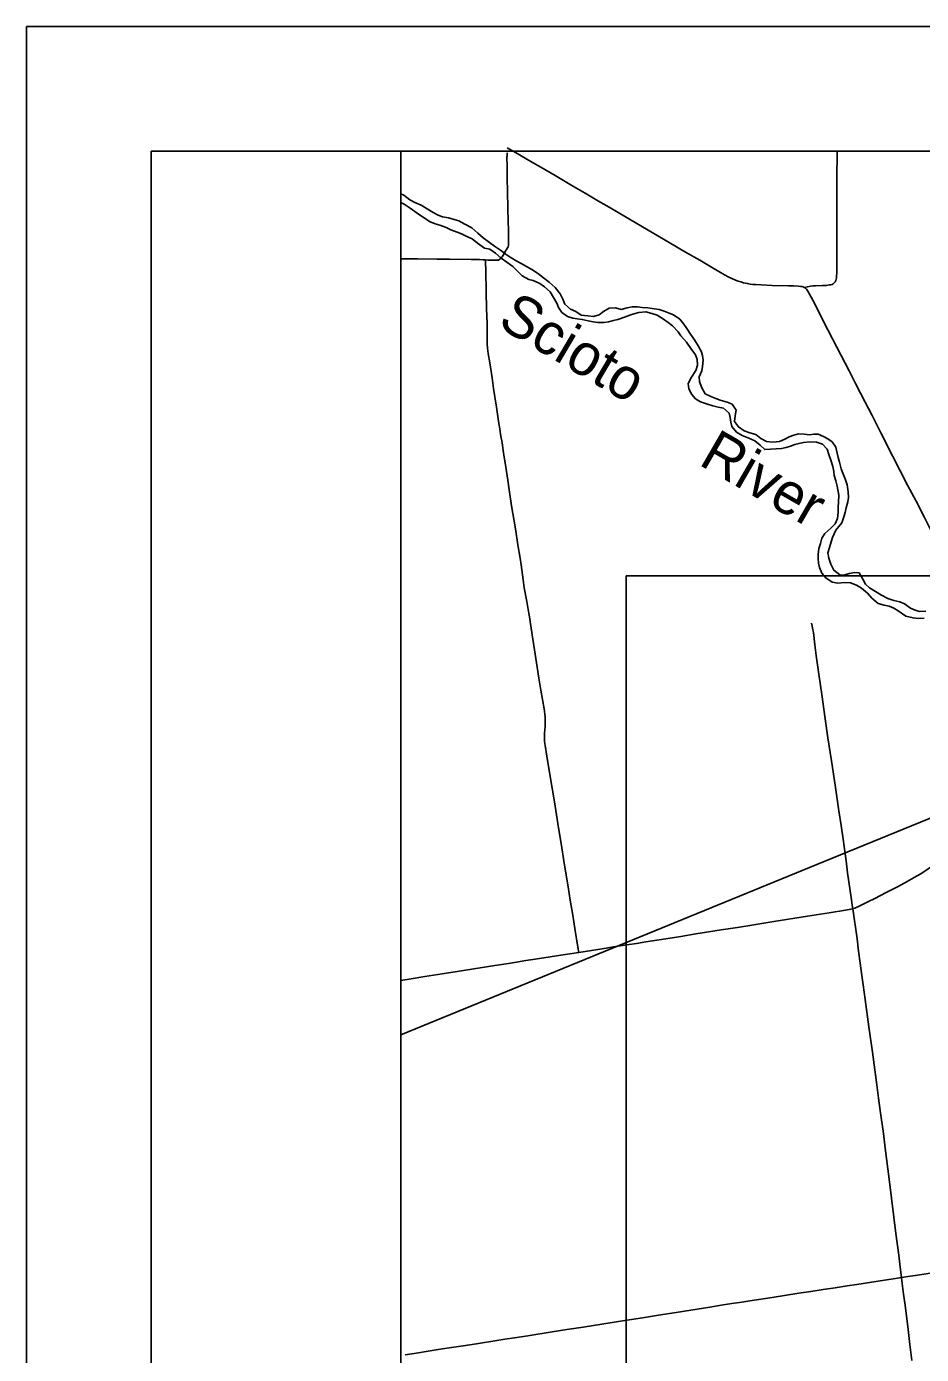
# Model space of a CAD drawing. Extents: x 0 to 680, y 0 to 440.
# Drawn here: x 0 to 71.7, y 333.5 to 440 of the extents above; entities that cross this region are included whole.
import ezdxf

# ---------------------------------------------------------------- set-up
doc = ezdxf.new("R2010")
doc.units = 0
for name, color, linetype in [('GM_X_County_Road', 7, 'Continuous'), ('GM_X_Major_River', 7, 'Continuous'), ('GM_X_Major_River_Text', 7, 'Continuous'), ('GM_X_Township_Road', 7, 'Continuous'), ('MT_P_Text', 7, 'Continuous'), ('RD_X_RR_2', 7, 'Continuous'), ('SH_Border', 7, 'Continuous'), ('SH_Cut_Line', 7, 'Continuous'), ('SH_Text', 7, 'Continuous')]:
    doc.layers.add(name, color=color, linetype=linetype)

msp = doc.modelspace()

# ---------------------------------------------------------------- linework, layer by layer
at = {"layer": 'GM_X_County_Road'}
for points in [[(38.61, 424.19), (38.61, 424.3), (38.61, 424.41), (38.6, 424.51), (38.6, 424.62), (38.6, 424.73), (38.6, 424.84), (38.59, 424.95), (38.59, 425.06), (38.59, 425.17), (38.58, 425.27), (38.58, 425.38), (38.58, 425.49), (38.57, 425.6), (38.57, 425.71), (38.57, 425.82), (38.57, 425.93), (38.57, 426.04), (38.56, 426.15), (38.56, 426.26), (38.55, 426.37), (38.55, 426.48), (38.55, 426.59), (38.55, 426.7), (38.54, 426.8), (38.54, 426.91), (38.54, 427.02), (38.54, 427.13), (38.54, 427.24), (38.53, 427.35), (38.53, 427.46), (38.53, 427.57), (38.53, 427.68), (38.53, 427.79), (38.53, 427.9), (38.53, 428.01), (38.52, 428.12), (38.52, 428.23), (38.52, 428.34), (38.52, 428.45), (38.52, 428.56), (38.52, 428.67), (38.52, 428.78), (38.52, 428.88), (38.52, 428.99), (38.52, 429.1), (38.51, 429.21), (38.51, 429.32), (38.51, 429.43), (38.51, 429.54), (38.52, 429.61), (38.52, 429.71), (38.52, 429.82), (38.52, 429.86)], [(38.52, 430.26), (38.67, 430.19), (39.05, 429.99), (40.56, 429.1), (41.22, 428.71), (42.36, 428.05), (43.85, 427.17), (44.78, 426.63), (45.85, 426), (46.7, 425.5), (48.02, 424.74), (48.78, 424.29), (49.82, 423.68), (51.51, 422.68), (52.83, 421.91), (53.97, 421.25), (54.91, 420.7), (55.48, 420.36), (55.95, 420.08), (56.24, 419.93), (56.54, 419.79), (56.84, 419.66), (57.05, 419.58), (57.26, 419.51), (57.47, 419.45), (57.79, 419.38), (58.01, 419.34), (58.23, 419.32), (58.45, 419.3), (58.89, 419.27), (59.76, 419.24), (61.07, 419.2), (61.51, 419.19), (61.84, 419.18), (62.05, 419.16), (62.16, 419.14), (62.26, 419.11), (62.32, 419.08)], [(38.31, 421.84), (38.36, 421.93), (38.4, 422), (38.47, 422.12), (38.56, 422.24), (38.61, 422.34), (38.63, 422.43), (38.64, 422.55), (38.64, 422.66), (38.64, 422.77), (38.63, 422.88), (38.63, 422.99), (38.64, 423.09), (38.63, 423.2), (38.63, 423.31), (38.63, 423.42), (38.63, 423.53), (38.62, 423.64), (38.62, 423.75), (38.62, 423.86), (38.62, 423.97), (38.61, 424.08), (38.61, 424.19)], [(36.79, 421.29), (36.98, 421.27), (37.18, 421.26), (37.33, 421.25), (37.66, 421.25), (37.83, 421.27), (37.95, 421.35), (38.03, 421.45), (38.12, 421.54), (38.21, 421.67), (38.28, 421.8), (38.31, 421.84)], [(30, 421.38), (30.49, 421.38), (31.37, 421.37), (32.9, 421.35), (33.89, 421.34), (35.64, 421.32), (36.3, 421.31), (36.59, 421.3), (36.79, 421.29)], [(62.32, 419.08), (62.36, 419.07), (62.44, 419.01), (62.52, 418.94), (62.58, 418.86), (62.64, 418.77), (62.9, 418.29), (63.16, 417.81), (63.89, 416.34), (65.3, 413.61), (65.94, 412.37), (66.45, 411.37), (66.85, 410.59), (67.21, 409.88), (67.75, 408.85), (68.48, 407.4), (69.45, 405.51), (70.63, 403.21), (71.3, 401.92), (71.95, 400.66), (72.5, 399.6), (73.05, 398.53), (73.79, 397.06), (74.31, 396.05)], [(44.26, 365.73), (44.78, 365.81), (46.29, 366.05), (47.05, 366.18), (47.59, 366.25), (48.13, 366.33), (48.89, 366.45), (49.64, 366.57), (50.72, 366.74), (51.59, 366.88), (52.45, 367.02), (53.64, 367.21), (54.5, 367.35), (55.69, 367.54), (56.99, 367.74), (58.29, 367.94), (59.91, 368.2), (62.61, 368.63), (64.34, 368.9), (65.64, 369.11), (66.07, 369.19), (66.23, 369.23)], [(30, 363.48), (30.84, 363.61), (31.92, 363.79), (33.32, 364.02), (34.51, 364.21), (36.35, 364.49), (37.54, 364.68), (38.62, 364.85), (39.27, 364.95), (40.02, 365.07), (40.78, 365.19), (41.97, 365.37), (42.83, 365.51), (44.26, 365.73)], [(70.97, 332.99), (70.81, 334.29), (70.66, 335.49), (70.42, 337.44), (70.3, 338.31), (70.16, 339.39), (70.13, 339.65)]]:
    msp.add_lwpolyline(points, dxfattribs=at)
at = {"layer": 'GM_X_Major_River'}
for points in [[(53.93, 411.54), (53.92, 411.89), (54.12, 412.38), (54.19, 412.72), (54.24, 413.25), (54.19, 413.6), (54.07, 413.95), (53.83, 414.38), (53.54, 414.87), (53.23, 415.32), (52.94, 415.78), (52.69, 416.12), (52.36, 416.54), (51.87, 416.87), (51.5, 417), (51.11, 417.17), (50.71, 417.29), (50.14, 417.39), (49.79, 417.43), (49.36, 417.47), (48.97, 417.52), (48.54, 417.51), (48.14, 417.43), (47.66, 417.31), (47.2, 417.44), (46.69, 417.4), (46.25, 417.14), (45.9, 416.87), (45.45, 416.73), (44.98, 416.79), (44.47, 416.86), (44.02, 417.13), (43.59, 417.33), (43.16, 417.72), (42.98, 418.14), (42.78, 418.57), (42.37, 419.07), (41.9, 419.5), (41.45, 419.84), (40.97, 420.23), (40.51, 420.52), (40.08, 420.76), (39.66, 421), (39.29, 421.19), (38.76, 421.5), (38.37, 421.77), (37.98, 422.07), (37.51, 422.38), (37.12, 422.68), (36.6, 423.06), (36.18, 423.42), (35.7, 423.85), (35.13, 424.16), (34.64, 424.41), (34.28, 424.53), (33.82, 424.65), (33.35, 424.74), (33, 424.86), (32.58, 425.09), (32.12, 425.39), (31.63, 425.66), (31.13, 425.88), (30.71, 426.11), (30.25, 426.47), (30, 426.58)], [(30, 425.89), (30.27, 425.75), (30.74, 425.43), (31.13, 425.16), (31.5, 424.89), (31.95, 424.59), (32.31, 424.36), (32.75, 424.17), (33.14, 424.06), (33.64, 423.87), (34.01, 423.7), (34.51, 423.5), (34.86, 423.36), (35.29, 423.17), (35.71, 422.96), (36.14, 422.62), (36.71, 422.23), (37.14, 422.14), (37.6, 421.83), (38.04, 421.41), (38.49, 421.1), (38.98, 420.74), (39.4, 420.32), (39.74, 420), (40.26, 419.72), (40.62, 419.63), (41.14, 419.4), (41.52, 419.13), (41.96, 418.71), (42.51, 417.82), (42.64, 417.47), (42.92, 417.07), (43.37, 416.73), (43.78, 416.6), (44.13, 416.55), (44.55, 416.51), (45.02, 416.4), (45.43, 416.32), (45.78, 416.27), (46.31, 416.26), (46.65, 416.31), (47.04, 416.42), (47.4, 416.49), (47.94, 416.7), (48.35, 416.84), (48.69, 416.96), (49.09, 417.06), (49.63, 417.11), (50.12, 416.99), (50.55, 416.85), (50.99, 416.58), (51.44, 416.27), (51.78, 416), (52.22, 415.51), (52.44, 415.18), (52.89, 414.68), (53.26, 414.17), (53.61, 413.66), (53.76, 413.28), (53.77, 412.83), (53.64, 412.42), (53.31, 411.87), (53.04, 411.38), (53.08, 410.95)], [(72.08, 393.1), (71.57, 393.09), (71.22, 393.18), (70.86, 393.35), (70.38, 393.69), (70.01, 393.85), (69.53, 393.95), (69.04, 394.12), (68.53, 394.4), (68.04, 394.69), (67.58, 394.98), (67.24, 395.28), (67.04, 395.67), (66.74, 396.17), (66.39, 396.21), (65.94, 396.13), (65.52, 395.99), (65.18, 396.03), (64.7, 396.38), (64.47, 396.87), (64.3, 397.35), (64.22, 397.79), (64.37, 398.2), (64.51, 398.66), (64.6, 399.02), (64.87, 399.59), (65.35, 400.2), (65.52, 400.67), (65.63, 401.03), (65.71, 401.4), (65.84, 401.87), (65.88, 402.23), (65.87, 402.67), (65.78, 403.23), (65.65, 403.63), (65.42, 404.17), (65.3, 404.53), (65.17, 405.05), (65.06, 405.44), (64.98, 405.78), (64.86, 406.26), (64.57, 406.69), (64.22, 406.94), (63.87, 407.11), (63.45, 407.29), (63.1, 407.29), (62.75, 407.26), (62.34, 407.29), (61.89, 407.34), (61.5, 407.23), (61.14, 407.09), (60.78, 406.89), (60.36, 406.71), (59.82, 406.65), (59.32, 406.72), (58.86, 406.95), (58.45, 407.28), (57.97, 407.41), (57.52, 407.57), (57.06, 407.88), (56.74, 408.31), (56.8, 408.78), (56.87, 409.24), (56.55, 409.72), (56.17, 409.86), (55.61, 410.02), (55.26, 410.17), (54.86, 410.32), (54.4, 410.55), (54.09, 411.08), (53.93, 411.54)], [(53.08, 410.95), (53.33, 410.49), (53.62, 410.14), (54.02, 409.9), (54.5, 409.74), (55.01, 409.58), (55.43, 409.47), (55.88, 409.38), (56.31, 409), (56.4, 408.65), (56.45, 408.26), (56.54, 407.91), (56.91, 407.47), (57.36, 407.19), (57.89, 406.97), (58.39, 406.78), (58.8, 406.43), (59.17, 406.06), (59.64, 406.09), (60.09, 406.12), (60.52, 406.15), (60.89, 406.22), (61.23, 406.35), (61.59, 406.47), (61.92, 406.56), (62.27, 406.63), (62.79, 406.69), (63.32, 406.67), (63.79, 406.49), (64.17, 406.09), (64.3, 405.67), (64.47, 405.21), (64.64, 404.71), (64.71, 404.32), (64.75, 403.99), (64.87, 403.55), (64.98, 403.13), (65.11, 402.42), (65.08, 401.86), (65.06, 401.46), (65.06, 401.02), (65, 400.55), (64.81, 400.1), (64.46, 399.75), (63.99, 399.34), (63.75, 398.96), (63.64, 398.52), (63.52, 398.13), (63.45, 397.66), (63.46, 397.33), (63.49, 396.95), (63.56, 396.61), (63.75, 396.14), (64.06, 395.77), (64.57, 395.42), (65.04, 395.34), (65.57, 395.41), (66.05, 395.37), (66.52, 395.19), (66.93, 394.95), (67.4, 394.56), (67.77, 394.14), (68.26, 393.73), (68.74, 393.58), (69.14, 393.5), (69.51, 393.35), (69.86, 393.13), (70.49, 392.69), (71.06, 392.56), (71.49, 392.52), (71.96, 392.54)]]:
    msp.add_lwpolyline(points, dxfattribs=at)
at = {"layer": 'GM_X_Township_Road'}
for points in [[(62.32, 419.08), (62.59, 419.13), (62.85, 419.17), (63.03, 419.19), (63.25, 419.21), (63.8, 419.23), (64.13, 419.24), (64.35, 419.27), (64.46, 419.29), (64.57, 419.32), (64.67, 419.37), (64.75, 419.44), (64.82, 419.52), (64.87, 419.62), (64.9, 419.73), (64.92, 419.84), (64.94, 420.39), (64.94, 420.72), (64.94, 421.92), (64.94, 424.22), (64.94, 424.88), (64.94, 425.54), (64.94, 426.52), (64.96, 427.83), (64.99, 429.91), (64.99, 430)], [(38.06, 406.93), (38.05, 406.96), (38, 407.3), (37.93, 407.73), (37.86, 408.16), (37.75, 408.92), (37.67, 409.46), (37.44, 410.97), (37.31, 411.83), (37.13, 413.02), (37.01, 413.78), (36.96, 414.21), (36.93, 414.54), (36.91, 414.87), (36.92, 415.41), (36.91, 415.63), (36.91, 416.18), (36.88, 417.38), (36.85, 418.69), (36.83, 419.35), (36.82, 419.79), (36.81, 420.55), (36.8, 420.99), (36.79, 421.29)], [(44.26, 365.73), (44.2, 366.15), (43.95, 367.66), (43.78, 368.73), (43.58, 369.92), (43.41, 371), (43.13, 372.73), (42.9, 374.13), (42.59, 376.07), (42.31, 377.8), (41.97, 379.84), (41.71, 381.46), (41.57, 382.33), (41.53, 382.65), (41.52, 382.87), (41.52, 383.09), (41.52, 383.31), (41.57, 383.85), (41.58, 384.18), (41.58, 384.4), (41.57, 384.61), (41.54, 384.83), (41.48, 385.26), (41.36, 386.02), (41.23, 386.77), (41.07, 387.74), (40.94, 388.61), (40.72, 390.01), (40.58, 390.87), (40.28, 392.82), (40.2, 393.25), (40.09, 393.89), (39.9, 394.97), (39.8, 395.62), (39.64, 396.81), (39.56, 397.35), (39.38, 398.43), (39.18, 399.72), (38.88, 401.56), (38.68, 402.85), (38.57, 403.61), (38.36, 405.01), (38.29, 405.45), (38.2, 405.98), (38.14, 406.42), (38.06, 406.93)], [(66.23, 369.23), (66.19, 369.51), (66.12, 369.94), (65.81, 372.11), (65.69, 373.09), (65.62, 373.63), (65.45, 374.82), (65.29, 375.91), (65.11, 377.1), (64.81, 379.15), (64.52, 381.1), (64.24, 382.94), (64.03, 384.46), (63.75, 386.41), (63.51, 388.04), (63.3, 389.55), (63.19, 390.41), (63.07, 391.38), (63.04, 391.61), (62.98, 391.91), (62.93, 392.14)], [(30.35, 333.44), (31.43, 333.61), (31.86, 333.68), (32.83, 333.84), (33.7, 333.98), (35, 334.17), (36.08, 334.34), (37.7, 334.6), (38.35, 334.7), (39.1, 334.82), (40.18, 334.98), (42.13, 335.29), (43.32, 335.48), (44.61, 335.68), (47.6, 336.15), (49.38, 336.43), (50.66, 336.63), (52.07, 336.85), (53.26, 337.03), (54.77, 337.27), (55.85, 337.45), (56.71, 337.59), (57.15, 337.65), (58.33, 337.84), (59.42, 338), (60.6, 338.19), (61.9, 338.39), (62.87, 338.54), (63.85, 338.69), (64.82, 338.83), (65.79, 338.98), (66.55, 339.1), (68.07, 339.32), (69.65, 339.57), (70.13, 339.65)]]:
    msp.add_lwpolyline(points, dxfattribs=at)
at = {"layer": 'MT_P_Text'}
for points in [[(68.2, 370.17), (68.23, 370.18), (69.13, 370.64), (69.75, 370.96), (70.39, 371.3), (71.16, 371.74), (71.63, 372.02), (72.09, 372.31), (72.55, 372.62), (73.08, 372.99), (73.61, 373.39), (74.12, 373.79), (74.24, 373.88)], [(66.23, 369.23), (66.28, 369.24), (66.39, 369.28), (66.49, 369.32), (66.69, 369.41), (67.28, 369.7), (68.2, 370.17)], [(70.13, 339.65), (70.03, 340.47), (69.91, 341.45), (69.68, 343.19), (69.52, 344.49), (69.14, 347.53), (68.83, 350.02), (68.68, 351.21), (68.43, 353.06), (68.3, 354.03), (68.15, 355.12), (67.99, 356.31), (67.8, 357.72), (67.52, 359.77), (67.23, 361.94), (67.06, 363.13), (66.96, 363.89), (66.82, 364.87), (66.7, 365.84), (66.57, 366.82), (66.23, 369.23)], [(88.26, 342.4), (88.07, 342.37), (87.53, 342.29), (85.8, 342.03), (84.69, 341.86), (82.82, 341.58), (81.36, 341.36), (80.17, 341.17), (79.09, 341.01), (77.69, 340.79), (76.5, 340.61), (74.98, 340.38), (73.15, 340.11), (72.28, 339.98), (71.41, 339.85), (70.66, 339.73), (70.13, 339.65)]]:
    msp.add_lwpolyline(points, dxfattribs=at)
at = {"layer": 'RD_X_RR_2'}
msp.add_lwpolyline([(199.79, 400.86), (177.18, 401.05), (155.89, 401.21), (145.78, 401.29), (141.07, 401.32), (139.99, 401.32), (139.09, 401.28), (138.07, 401.22), (136.91, 401.13), (136.06, 401.04), (135.32, 400.93), (134.31, 400.77), (133.28, 400.58), (132.35, 400.38), (131.12, 400.08), (129.99, 399.76), (129.07, 399.46), (128.04, 399.12), (127.16, 398.8), (125.42, 398.09), (104.89, 389.72), (80.55, 379.82), (63.35, 372.77), (30, 359.11)], dxfattribs=at)
at = {"layer": 'SH_Border'}
for points in [[(10, 430), (30, 430), (30, 10), (10, 10)], [(30, 430), (670, 430), (670, 10), (30, 10)]]:
    msp.add_lwpolyline(points, close=True, dxfattribs=at)
at = {"layer": 'SH_Cut_Line'}
msp.add_lwpolyline([(0, 0), (680, 0), (680, 440), (0, 440)], close=True, dxfattribs=at)
at = {"layer": 'SH_Text'}
for points in [[(30, 430), (466.92, 430), (466.92, 291.27), (342.9, 138.72), (30, 138.72)], [(48.07, 395.94), (126.26, 395.94), (126.26, 313.95), (48.07, 313.95)]]:
    msp.add_lwpolyline(points, close=True, dxfattribs=at)

# ---------------------------------------------------------------- texts
at = {"layer": 'GM_X_Major_River_Text'}
for s, rotation, p in [('Scioto', 329.4621, (37.65, 415.99)), ('River', 330.0189, (53.78, 404.91))]:
    msp.add_text(s, height=3.334, rotation=rotation, dxfattribs=at).set_placement(p)

doc.saveas('drawing.dxf')
